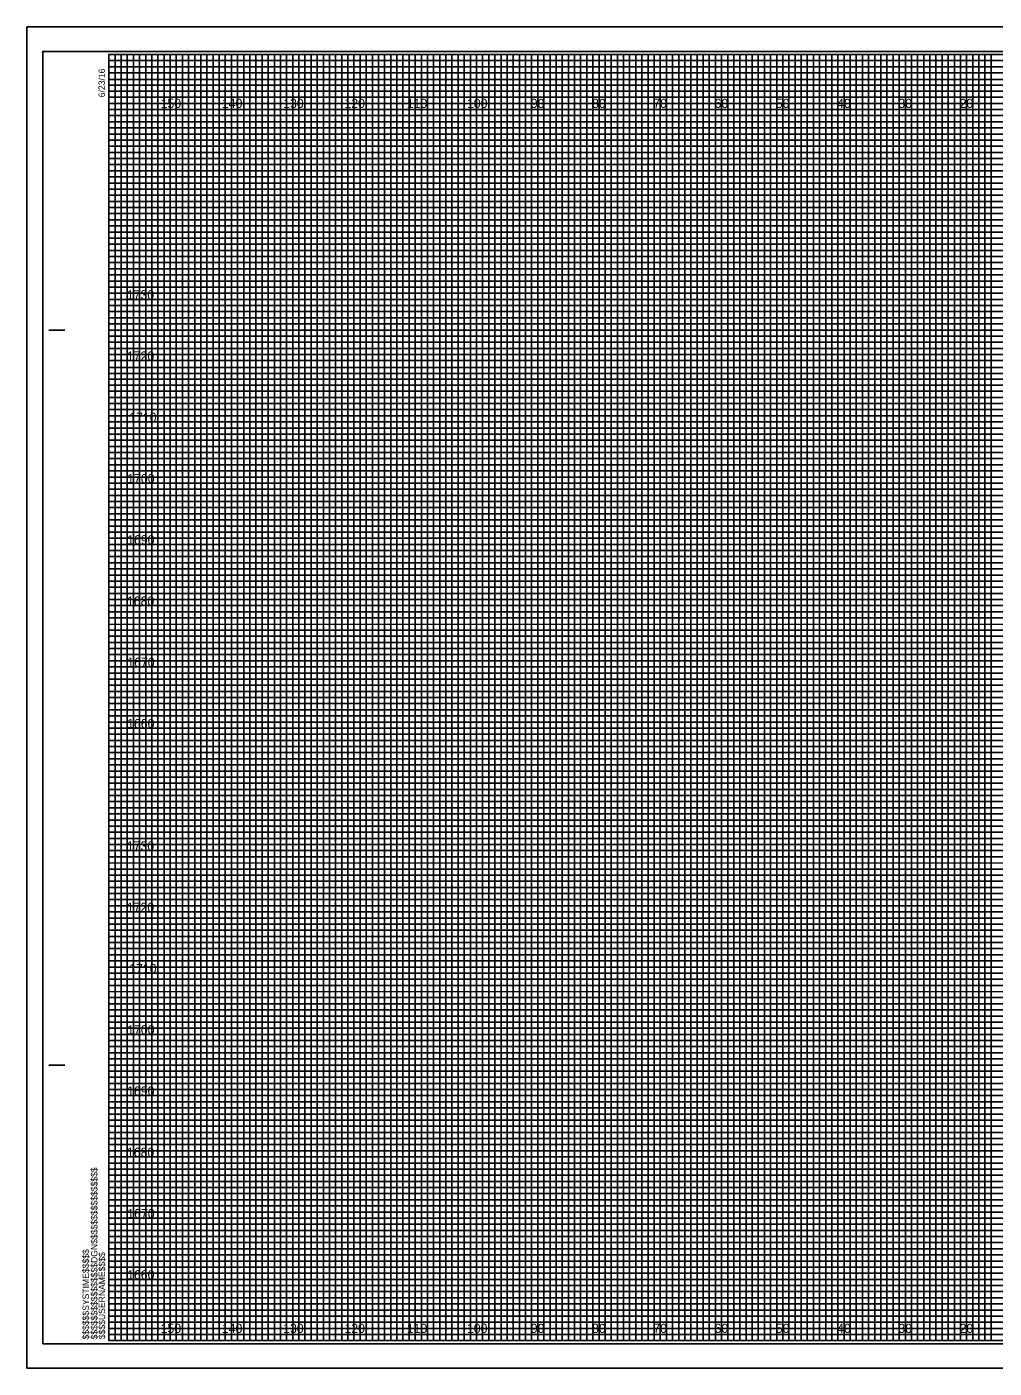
# Model space of a CAD drawing. Extents: x 656 to 993, y -2 to 2857.
# Drawn here: x 656.3 to 814.2, y 218.3 to 437.3 of the extents above; entities that cross this region are included whole.
import ezdxf

# ---------------------------------------------------------------- set-up
doc = ezdxf.new("R2010")
doc.units = 0
for name, color, linetype in [('Prop RDY Alternate Text Blue', 7, 'Continuous'), ('Prop Retaining Wall', 7, 'Continuous'), ('Prop SS Cut Line', 7, 'Continuous'), ('Prop SS Fill Line', 7, 'Continuous'), ('Prop SS Transition Line', 7, 'Continuous'), ('Raster_Level_0', 7, 'Continuous'), ('Raster_Level_3', 7, 'Continuous'), ('Scratch_Level_3', 7, 'Continuous'), ('Scratch_Level_7', 7, 'Continuous'), ('Typical Guardrail CELL', 7, 'Continuous'), ('Typical Text Asphalt at Bridge Approach CELL', 7, 'Continuous')]:
    doc.layers.add(name, color=color, linetype=linetype)

msp = doc.modelspace()

# ---------------------------------------------------------------- linework, layer by layer
at = {"layer": 'Prop RDY Alternate Text Blue'}
for p, q in [((679.74, 222.8), (679.74, 432.8)), ((689.74, 222.8), (689.74, 432.8)), ((699.74, 222.8), (699.74, 432.8)), ((709.74, 222.8), (709.74, 432.8)), ((719.74, 222.8), (719.74, 432.8)), ((729.74, 222.8), (729.74, 432.8)), ((739.74, 222.8), (739.74, 432.8)), ((749.74, 222.8), (749.74, 432.8)), ((759.74, 222.8), (759.74, 432.8)), ((769.74, 222.8), (769.74, 432.8)), ((779.74, 222.8), (779.74, 432.8)), ((789.74, 222.8), (789.74, 432.8)), ((799.74, 222.8), (799.74, 432.8)), ((809.74, 222.8), (809.74, 432.8)), ((669.74, 422.8), (989.74, 422.8)), ((669.74, 412.8), (989.74, 412.8)), ((669.74, 402.8), (989.74, 402.8)), ((669.74, 392.8), (989.74, 392.8)), ((669.74, 382.8), (989.74, 382.8)), ((669.74, 372.8), (989.74, 372.8)), ((669.74, 362.8), (989.74, 362.8)), ((669.74, 352.8), (989.74, 352.8)), ((669.74, 342.8), (989.74, 342.8)), ((669.74, 332.8), (989.74, 332.8)), ((669.74, 322.8), (989.74, 322.8)), ((669.74, 312.8), (989.74, 312.8)), ((669.74, 302.8), (989.74, 302.8)), ((669.74, 292.8), (989.74, 292.8)), ((669.74, 282.8), (989.74, 282.8)), ((669.74, 272.8), (989.74, 272.8)), ((669.74, 262.8), (989.74, 262.8)), ((669.74, 252.8), (989.74, 252.8)), ((669.74, 242.8), (989.74, 242.8)), ((669.74, 232.8), (989.74, 232.8))]:
    msp.add_line(p, q, dxfattribs=at)
at = {"layer": 'Prop Retaining Wall'}
for p, q in [((659.94, 387.8), (662.44, 387.8)), ((660.04, 387.8), (662.54, 387.8)), ((659.94, 267.8), (662.44, 267.8)), ((660.04, 267.8), (662.54, 267.8)), ((669.74, 222.8), (669.74, 222.8)), ((669.74, 222.8), (669.74, 222.8)), ((669.74, 222.8), (669.74, 222.8)), ((669.74, 222.8), (669.74, 222.8)), ((669.74, 222.8), (669.74, 222.8)), ((669.74, 222.8), (669.74, 222.8)), ((669.74, 222.8), (669.74, 222.8))]:
    msp.add_line(p, q, dxfattribs=at)
msp.add_lwpolyline([(989.74, 432.8), (669.74, 432.8), (669.74, 222.8), (989.74, 222.8)], close=True, dxfattribs=at)
at = {"layer": 'Prop SS Cut Line'}
for points in [[(669.74, 432.8), (674.74, 432.8), (674.74, 222.8), (684.74, 222.8), (684.74, 432.8), (694.74, 432.8), (694.74, 222.8), (704.74, 222.8), (704.74, 432.8), (714.74, 432.8), (714.74, 222.8), (724.74, 222.8), (724.74, 432.8), (734.74, 432.8), (734.74, 222.8), (744.74, 222.8), (744.74, 432.8), (754.74, 432.8), (754.74, 222.8), (764.74, 222.8), (764.74, 432.8), (774.74, 432.8), (774.74, 222.8), (784.74, 222.8), (784.74, 432.8), (794.74, 432.8), (794.74, 222.8), (804.74, 222.8), (804.74, 432.8), (814.74, 432.8)], [(669.74, 427.8), (944.74, 427.8)], [(669.74, 407.8), (989.74, 407.8), (989.74, 417.8), (669.74, 417.8)], [(669.74, 387.8), (989.74, 387.8), (989.74, 397.8), (669.74, 397.8)], [(669.74, 367.8), (989.74, 367.8), (989.74, 377.8), (669.74, 377.8)], [(669.74, 347.8), (989.74, 347.8), (989.74, 357.8), (669.74, 357.8)], [(669.74, 327.8), (989.74, 327.8), (989.74, 337.8), (669.74, 337.8)], [(669.74, 307.8), (989.74, 307.8), (989.74, 317.8), (669.74, 317.8)], [(669.74, 287.8), (989.74, 287.8), (989.74, 297.8), (669.74, 297.8)], [(669.74, 267.8), (989.74, 267.8), (989.74, 277.8), (669.74, 277.8)], [(669.74, 247.8), (989.74, 247.8), (989.74, 257.8), (669.74, 257.8)], [(669.74, 227.8), (989.74, 227.8), (989.74, 237.8), (669.74, 237.8)]]:
    msp.add_lwpolyline(points, dxfattribs=at)
at = {"layer": 'Prop SS Fill Line'}
for p, q in [((679.74, 432.8), (669.74, 432.8)), ((679.74, 222.8), (679.74, 432.8)), ((699.74, 432.8), (689.74, 432.8)), ((689.74, 432.8), (689.74, 222.8)), ((699.74, 222.8), (699.74, 432.8)), ((719.74, 432.8), (709.74, 432.8)), ((709.74, 432.8), (709.74, 222.8)), ((719.74, 222.8), (719.74, 432.8)), ((739.74, 432.8), (729.74, 432.8)), ((729.74, 432.8), (729.74, 222.8)), ((739.74, 222.8), (739.74, 432.8)), ((759.74, 432.8), (749.74, 432.8)), ((749.74, 432.8), (749.74, 222.8)), ((759.74, 222.8), (759.74, 432.8)), ((779.74, 432.8), (769.74, 432.8)), ((769.74, 432.8), (769.74, 222.8)), ((779.74, 222.8), (779.74, 432.8)), ((799.74, 432.8), (789.74, 432.8)), ((789.74, 432.8), (789.74, 222.8)), ((799.74, 222.8), (799.74, 432.8)), ((819.74, 432.8), (809.74, 432.8)), ((809.74, 432.8), (809.74, 222.8)), ((689.74, 222.8), (679.74, 222.8)), ((709.74, 222.8), (699.74, 222.8)), ((729.74, 222.8), (719.74, 222.8)), ((749.74, 222.8), (739.74, 222.8)), ((769.74, 222.8), (759.74, 222.8)), ((789.74, 222.8), (779.74, 222.8)), ((809.74, 222.8), (799.74, 222.8))]:
    msp.add_line(p, q, dxfattribs=at)
for points in [[(669.74, 422.8), (989.74, 422.8), (989.74, 412.8), (669.74, 412.8)], [(669.74, 402.8), (989.74, 402.8), (989.74, 392.8), (669.74, 392.8)], [(669.74, 382.8), (989.74, 382.8), (989.74, 372.8), (669.74, 372.8)], [(669.74, 362.8), (989.74, 362.8), (989.74, 352.8), (669.74, 352.8)], [(669.74, 342.8), (989.74, 342.8), (989.74, 332.8), (669.74, 332.8)], [(669.74, 322.8), (989.74, 322.8), (989.74, 312.8), (669.74, 312.8)], [(669.74, 302.8), (989.74, 302.8), (989.74, 292.8), (669.74, 292.8)], [(669.74, 282.8), (989.74, 282.8), (989.74, 272.8), (669.74, 272.8)], [(669.74, 262.8), (989.74, 262.8), (989.74, 252.8), (669.74, 252.8)], [(669.74, 242.8), (989.74, 242.8), (989.74, 232.8), (669.74, 232.8)]]:
    msp.add_lwpolyline(points, dxfattribs=at)
at = {"layer": 'Prop SS Transition Line'}
for p, q in [((669.74, 431.8), (929.74, 431.8)), ((929.74, 430.78), (669.74, 430.78)), ((669.74, 430.78), (669.74, 429.8)), ((669.74, 429.8), (929.74, 429.8)), ((929.74, 428.69), (669.74, 428.69)), ((669.74, 428.69), (669.74, 426.8)), ((669.74, 426.8), (989.74, 426.8))]:
    msp.add_line(p, q, dxfattribs=at)
for points in [[(669.74, 425.8), (939.74, 425.8), (989.74, 425.8), (989.74, 424.8), (669.74, 424.8)], [(669.74, 423.8), (989.74, 423.8), (989.74, 421.8), (669.74, 421.8)], [(669.74, 420.8), (989.74, 420.8), (989.74, 419.8), (669.74, 419.78)], [(669.74, 418.8), (989.74, 418.8), (989.74, 416.8), (669.74, 416.8)], [(669.74, 415.8), (989.74, 415.8), (989.74, 414.8), (669.74, 414.8)], [(669.74, 413.8), (989.74, 413.8), (989.74, 411.8), (669.74, 411.8)], [(669.74, 410.8), (989.74, 410.8), (989.74, 409.8), (669.74, 409.8)], [(669.74, 408.8), (989.74, 408.8), (989.74, 406.8), (669.74, 406.8)], [(669.74, 405.8), (989.74, 405.8), (989.74, 404.8), (669.74, 404.8)], [(669.74, 403.8), (989.74, 403.8), (989.74, 401.8), (669.74, 401.8)], [(669.74, 400.8), (989.74, 400.8), (989.74, 399.8), (669.74, 399.8)], [(669.74, 398.8), (989.74, 398.8), (989.74, 396.75), (989.74, 395.8), (989.74, 394.8), (669.74, 394.8)], [(669.74, 396.8), (989.74, 396.8), (989.74, 395.8), (669.74, 395.8)], [(669.74, 393.8), (989.74, 393.8), (989.74, 391.8), (669.74, 391.83)], [(669.74, 391.83), (989.74, 391.8), (989.74, 390.8), (669.74, 390.8)], [(669.74, 389.8), (989.74, 389.8), (989.74, 388.8), (669.74, 388.8)], [(669.74, 386.8), (989.74, 386.8), (989.74, 385.8), (669.74, 385.8)], [(669.74, 384.8), (989.74, 384.8), (989.74, 383.8), (669.74, 383.8)], [(669.67, 381.69), (989.74, 381.69), (989.74, 380.68), (669.67, 380.68)], [(669.74, 379.8), (989.74, 379.8), (989.74, 378.8), (669.74, 378.8)], [(669.74, 376.8), (989.74, 376.8), (989.74, 375.8), (669.74, 375.8)], [(669.74, 374.8), (989.74, 374.8), (989.74, 373.8), (669.74, 373.8)], [(669.74, 371.8), (989.74, 371.8), (989.74, 370.8), (669.74, 370.8)], [(669.74, 369.8), (989.74, 369.8), (989.74, 368.8), (669.74, 368.8)], [(669.74, 366.8), (989.74, 366.8), (989.74, 365.8), (669.74, 365.8)], [(669.74, 364.8), (989.74, 364.8), (989.74, 363.8), (669.74, 363.8)], [(669.74, 361.8), (989.74, 361.8), (989.73, 360.78), (669.74, 360.8)], [(669.74, 359.8), (989.74, 359.8), (989.74, 358.8), (669.74, 358.8)], [(669.74, 356.8), (989.74, 356.8), (989.74, 355.8), (669.74, 355.8)], [(669.74, 354.8), (989.74, 354.8), (989.74, 353.8), (669.74, 353.8)], [(669.74, 351.8), (989.74, 351.8), (989.74, 350.8), (669.74, 350.8)], [(669.74, 349.8), (989.74, 349.8), (989.74, 348.8), (669.74, 348.8)], [(669.74, 346.8), (989.74, 346.8), (989.74, 345.8), (669.74, 345.8)], [(669.74, 344.8), (989.74, 344.8), (989.74, 343.8), (669.74, 343.8)], [(669.74, 341.8), (989.74, 341.8), (989.74, 340.8), (669.74, 340.8)], [(669.74, 339.79), (989.81, 339.71), (989.74, 338.8), (669.74, 338.8)], [(669.74, 336.8), (989.74, 336.8), (989.74, 335.8), (669.74, 335.8)], [(669.74, 334.8), (989.74, 334.8), (989.74, 333.8), (669.74, 333.8)], [(669.74, 331.8), (989.74, 331.8), (989.74, 330.8), (669.74, 330.8)], [(669.74, 329.8), (989.74, 329.8), (989.74, 328.8), (669.74, 328.8)], [(669.74, 326.8), (989.74, 326.8), (989.74, 325.8), (669.74, 325.8)], [(669.74, 324.8), (989.74, 324.8), (989.74, 323.8), (669.74, 323.8)], [(669.74, 321.8), (989.74, 321.8), (989.74, 320.8), (669.74, 320.8)], [(669.74, 319.8), (989.74, 319.8), (989.74, 318.8), (669.74, 318.8)], [(669.74, 316.8), (989.74, 316.8), (989.74, 315.8), (669.74, 315.8)], [(669.74, 314.8), (989.74, 314.8), (989.74, 313.8), (669.74, 313.8)], [(669.74, 311.8), (989.74, 311.8), (989.74, 310.8), (669.74, 310.8)], [(669.74, 309.8), (989.74, 309.8), (989.74, 308.8), (669.74, 308.8)], [(669.74, 306.8), (989.74, 306.8), (989.74, 305.8), (669.74, 305.8)], [(669.74, 304.8), (989.74, 304.8), (989.74, 303.8), (669.74, 303.8)], [(669.74, 301.8), (989.74, 301.8), (989.73, 300.78), (669.74, 300.8)], [(669.74, 299.8), (989.74, 299.8), (989.74, 298.8), (669.74, 298.8)], [(669.74, 296.8), (989.74, 296.8), (989.74, 295.8), (669.74, 295.8)], [(669.74, 294.8), (989.74, 294.8), (989.74, 293.8), (669.74, 293.8)], [(669.74, 291.8), (989.74, 291.8), (989.74, 290.8), (669.74, 290.8)], [(669.74, 289.8), (989.74, 289.8), (989.74, 288.8), (669.74, 288.8)], [(669.74, 286.8), (989.74, 286.8), (989.74, 285.8), (669.74, 285.8)], [(669.74, 284.8), (989.74, 284.8), (989.74, 283.8), (669.74, 283.8)], [(669.74, 281.8), (989.74, 281.8), (989.74, 280.8), (669.74, 280.8)], [(669.74, 279.79), (989.81, 279.71), (989.74, 278.8), (669.74, 278.8)], [(669.74, 276.8), (989.74, 276.8), (989.74, 275.8), (669.74, 275.8)], [(669.74, 274.8), (989.74, 274.8), (989.74, 273.8), (669.74, 273.8)], [(669.74, 271.8), (989.74, 271.8), (989.74, 270.8), (669.74, 270.8)], [(669.74, 269.8), (989.74, 269.8), (989.74, 268.8), (669.74, 268.8)], [(669.74, 266.8), (989.74, 266.8), (989.74, 265.8), (669.74, 265.8)], [(669.74, 264.8), (989.74, 264.8), (989.74, 263.8), (669.74, 263.8)], [(669.74, 261.8), (989.74, 261.8), (989.74, 260.8), (669.74, 260.8)], [(669.74, 259.8), (989.74, 259.8), (989.74, 258.8), (669.74, 258.8)], [(669.74, 256.8), (989.74, 256.8), (989.74, 255.8), (669.74, 255.8)], [(669.74, 254.8), (989.74, 254.8), (989.74, 253.8), (669.74, 253.8)], [(669.74, 251.8), (989.74, 251.8), (989.74, 250.8), (669.74, 250.8)], [(669.74, 249.8), (989.74, 249.8), (989.74, 248.8), (669.74, 248.8)], [(669.74, 246.8), (989.74, 246.8), (989.74, 245.8), (669.74, 245.8)], [(669.74, 244.8), (989.74, 244.8), (989.74, 243.8), (669.74, 243.8)], [(669.74, 241.8), (989.74, 241.8), (989.74, 240.8), (669.74, 240.8)], [(669.74, 239.8), (989.74, 239.8), (989.74, 238.8), (669.74, 238.8)], [(669.74, 236.8), (989.74, 236.8), (989.74, 235.8), (669.74, 235.8)], [(669.74, 234.8), (989.74, 234.8), (989.74, 233.8), (669.74, 233.8)], [(669.74, 231.8), (989.74, 231.8), (989.74, 230.8), (669.74, 230.8)], [(669.74, 229.8), (989.74, 229.8), (989.74, 228.8), (669.74, 228.8)], [(669.74, 226.8), (989.74, 226.8), (989.74, 225.8), (669.74, 225.8)], [(669.74, 224.8), (989.74, 224.8), (989.74, 223.8), (669.74, 223.8)]]:
    msp.add_lwpolyline(points, dxfattribs=at)
at = {"layer": 'Raster_Level_3'}
for points in [[(669.74, 222.8), (670.74, 222.8), (670.74, 432.8), (671.74, 432.8), (671.74, 222.8)], [(671.74, 222.8), (672.74, 222.8), (672.74, 432.8), (673.74, 432.8), (673.74, 222.8)], [(674.74, 222.8), (675.74, 222.8), (675.74, 432.8), (676.74, 432.8), (676.74, 222.8)], [(676.74, 222.8), (677.74, 222.8), (677.74, 432.8), (678.74, 432.8), (678.74, 222.8)], [(679.74, 222.8), (680.74, 222.8), (680.74, 432.8), (681.74, 432.8), (681.74, 222.8)], [(681.74, 222.8), (682.74, 222.8), (682.74, 432.8), (683.74, 432.8), (683.74, 222.8)], [(684.74, 222.8), (685.74, 222.8), (685.74, 432.8), (686.74, 432.8), (686.74, 222.8)], [(686.74, 222.8), (687.74, 222.8), (687.74, 432.8), (688.74, 432.8), (688.74, 222.8)], [(689.74, 222.8), (690.74, 222.8), (690.74, 432.8), (691.74, 432.8), (691.74, 222.8)], [(691.74, 222.8), (692.74, 222.8), (692.74, 432.8), (693.74, 432.8), (693.74, 222.8)], [(694.74, 222.8), (695.74, 222.8), (695.74, 432.8), (696.74, 432.8), (696.74, 222.8)], [(696.74, 222.8), (697.74, 222.8), (697.74, 432.8), (698.74, 432.8), (698.74, 222.8)], [(699.74, 222.8), (700.74, 222.8), (700.74, 432.8), (701.74, 432.8), (701.74, 222.8)], [(701.74, 222.8), (702.74, 222.8), (702.74, 432.8), (703.74, 432.8), (703.74, 222.8)], [(704.74, 222.8), (705.74, 222.8), (705.74, 432.8), (706.74, 432.8), (706.74, 222.8)], [(706.74, 222.8), (707.74, 222.8), (707.74, 432.8), (708.74, 432.8), (708.74, 222.8)], [(709.74, 222.8), (710.74, 222.8), (710.74, 432.8), (711.74, 432.8), (711.74, 222.8)], [(711.74, 222.8), (712.74, 222.8), (712.74, 432.8), (713.74, 432.8), (713.74, 222.8)], [(714.74, 222.8), (715.74, 222.8), (715.74, 432.8), (716.74, 432.8), (716.74, 222.8)], [(716.74, 222.8), (717.74, 222.8), (717.74, 432.8), (718.74, 432.8), (718.74, 222.8)], [(719.74, 222.8), (720.74, 222.8), (720.74, 432.8), (721.74, 432.8), (721.74, 222.8)], [(721.74, 222.8), (722.74, 222.8), (722.74, 432.8), (723.74, 432.8), (723.74, 222.8)], [(724.74, 222.8), (725.74, 222.8), (725.74, 432.8), (726.74, 432.8), (726.74, 222.8)], [(726.74, 222.8), (727.74, 222.8), (727.74, 432.8), (728.74, 432.8), (728.74, 222.8)], [(729.74, 222.8), (730.74, 222.8), (730.74, 432.8), (731.74, 432.8), (731.74, 222.8)], [(731.74, 222.8), (732.74, 222.8), (732.74, 432.8), (733.74, 432.8), (733.74, 222.8)], [(734.74, 222.8), (735.74, 222.8), (735.74, 432.8), (736.74, 432.8), (736.74, 222.8)], [(736.74, 222.8), (737.74, 222.8), (737.74, 432.8), (738.74, 432.8), (738.74, 222.8)], [(739.74, 222.8), (740.74, 222.8), (740.74, 432.8), (741.74, 432.8), (741.74, 222.8)], [(741.74, 222.8), (742.74, 222.8), (742.74, 432.8), (743.74, 432.8), (743.74, 222.8)], [(744.74, 222.8), (745.74, 222.8), (745.74, 432.8), (746.74, 432.8), (746.74, 222.8)], [(746.74, 222.8), (747.74, 222.8), (747.74, 432.8), (748.74, 432.8), (748.74, 222.8)], [(749.74, 222.8), (750.74, 222.8), (750.74, 432.8), (751.74, 432.8), (751.74, 222.8)], [(751.74, 222.8), (752.74, 222.8), (752.74, 432.8), (753.74, 432.8), (753.74, 222.8)], [(754.74, 222.8), (755.74, 222.8), (755.74, 432.8), (756.74, 432.8), (756.74, 222.8)], [(756.74, 222.8), (757.74, 222.8), (757.74, 432.8), (758.74, 432.8), (758.74, 222.8)], [(759.74, 222.8), (760.74, 222.8), (760.74, 432.8), (761.74, 432.8), (761.74, 222.8)], [(761.74, 222.8), (762.74, 222.8), (762.74, 432.8), (763.74, 432.8), (763.74, 222.8)], [(764.74, 222.8), (765.74, 222.8), (765.74, 432.8), (766.74, 432.8), (766.74, 222.8)], [(766.74, 222.8), (767.74, 222.8), (767.74, 432.8), (768.74, 432.8), (768.74, 222.8)], [(769.74, 222.8), (770.74, 222.8), (770.74, 432.8), (771.74, 432.8), (771.74, 222.8)], [(771.74, 222.8), (772.74, 222.8), (772.74, 432.8), (773.74, 432.8), (773.74, 222.8)], [(774.74, 222.8), (775.74, 222.8), (775.74, 432.8), (776.74, 432.8), (776.74, 222.8)], [(776.74, 222.8), (777.74, 222.8), (777.74, 432.8), (778.74, 432.8), (778.74, 222.8)], [(779.74, 222.8), (780.74, 222.8), (780.74, 432.8), (781.74, 432.8), (781.74, 222.8)], [(781.74, 222.8), (782.74, 222.8), (782.74, 432.8), (783.74, 432.8), (783.74, 222.8)], [(784.74, 222.8), (785.74, 222.8), (785.74, 432.8), (786.74, 432.8), (786.74, 222.8)], [(786.74, 222.8), (787.74, 222.8), (787.74, 432.8), (788.74, 432.8), (788.74, 222.8)], [(789.74, 222.8), (790.74, 222.8), (790.74, 432.8), (791.74, 432.8), (791.74, 222.8)], [(791.74, 222.8), (792.74, 222.8), (792.74, 432.8), (793.74, 432.8), (793.74, 222.8)], [(794.74, 222.8), (795.74, 222.8), (795.74, 432.8), (796.74, 432.8), (796.74, 222.8)], [(796.74, 222.8), (797.74, 222.8), (797.74, 432.8), (798.74, 432.8), (798.74, 222.8)], [(799.74, 222.8), (800.74, 222.8), (800.74, 432.8), (801.74, 432.8), (801.74, 222.8)], [(801.74, 222.8), (802.74, 222.8), (802.74, 432.8), (803.74, 432.8), (803.74, 222.8)], [(804.74, 222.8), (805.74, 222.8), (805.74, 432.8), (806.74, 432.8), (806.74, 222.8)], [(806.74, 222.8), (807.74, 222.8), (807.74, 432.8), (808.74, 432.8), (808.74, 222.8)], [(809.74, 222.8), (810.74, 222.8), (810.74, 432.8), (811.74, 432.8), (811.74, 222.8)], [(811.74, 222.8), (812.74, 222.8), (812.74, 432.8), (813.74, 432.8), (813.74, 222.8)]]:
    msp.add_lwpolyline(points, dxfattribs=at)
at = {"layer": 'Scratch_Level_7'}
msp.add_lwpolyline([(656.34, 218.3), (993.04, 218.3), (993.04, 437.3), (656.34, 437.3)], close=True, dxfattribs=at)
at = {"layer": 'Typical Guardrail CELL'}
msp.add_lwpolyline([(658.94, 222.3), (992.14, 222.3), (992.14, 433.3), (658.94, 433.3)], close=True, dxfattribs=at)
at = {"layer": 'Typical Text Asphalt at Bridge Approach CELL'}
for p, q in [((993.04, 437.3), (656.34, 437.3)), ((656.34, 437.3), (656.34, 218.3)), ((656.34, 218.3), (993.04, 218.3))]:
    msp.add_line(p, q, dxfattribs=at)

# ---------------------------------------------------------------- texts
at = {"layer": 'Prop Retaining Wall'}
for s, p in [('6/23/16', (669.09, 425.8)), ('$$$$$$$$$$$$$$$$DGN$$$$$$$$$$$$$$$$', (667.86, 222.98)), ('$$$$$$SYSTIME$$$$$', (666.48, 222.98)), ('$$$$USERNAME$$$$', (669.12, 223.03))]:
    msp.add_text(s, height=1.05, rotation=90, dxfattribs=at).set_placement(p)
at = {"layer": 'Raster_Level_0'}
for s, p in [('150', (678.18, 424.05)), ('140', (688.18, 424.05)), ('130', (698.18, 424.05)), ('120', (708.18, 424.05)), ('110', (718.36, 424.05)), ('100', (728.18, 424.05)), ('90', (738.6, 424.05)), ('80', (748.6, 424.05)), ('70', (758.6, 424.05)), ('60', (768.6, 424.05)), ('50', (778.6, 424.05)), ('40', (788.6, 424.05)), ('30', (798.6, 424.05)), ('20', (808.6, 424.05)), ('150', (678.18, 224.05)), ('140', (688.18, 224.05)), ('130', (698.18, 224.05)), ('120', (708.18, 224.05)), ('110', (718.36, 224.05)), ('100', (728.18, 224.05)), ('90', (738.6, 224.05)), ('80', (748.6, 224.05)), ('70', (758.6, 224.05)), ('60', (768.6, 224.05)), ('50', (778.6, 224.05)), ('40', (788.6, 224.05)), ('30', (798.6, 224.05)), ('20', (808.6, 224.05))]:
    msp.add_text(s, height=1.5, dxfattribs=at).set_placement(p)
at = {"layer": 'Scratch_Level_3'}
for s, p in [('1730', (672.66, 392.8)), ('1720', (672.67, 382.8)), ('1710', (673.05, 372.8)), ('1700', (672.72, 362.8)), ('1690', (672.71, 352.8)), ('1680', (672.68, 342.8)), ('1670', (672.74, 332.8)), ('1660', (672.71, 322.8)), ('1730', (672.66, 302.8)), ('1720', (672.67, 292.8)), ('1710', (673.05, 282.8)), ('1700', (672.72, 272.8)), ('1690', (672.71, 262.8)), ('1680', (672.68, 252.8)), ('1670', (672.74, 242.8)), ('1660', (672.71, 232.8))]:
    msp.add_text(s, height=1.5, dxfattribs=at).set_placement(p)

doc.saveas('drawing.dxf')
